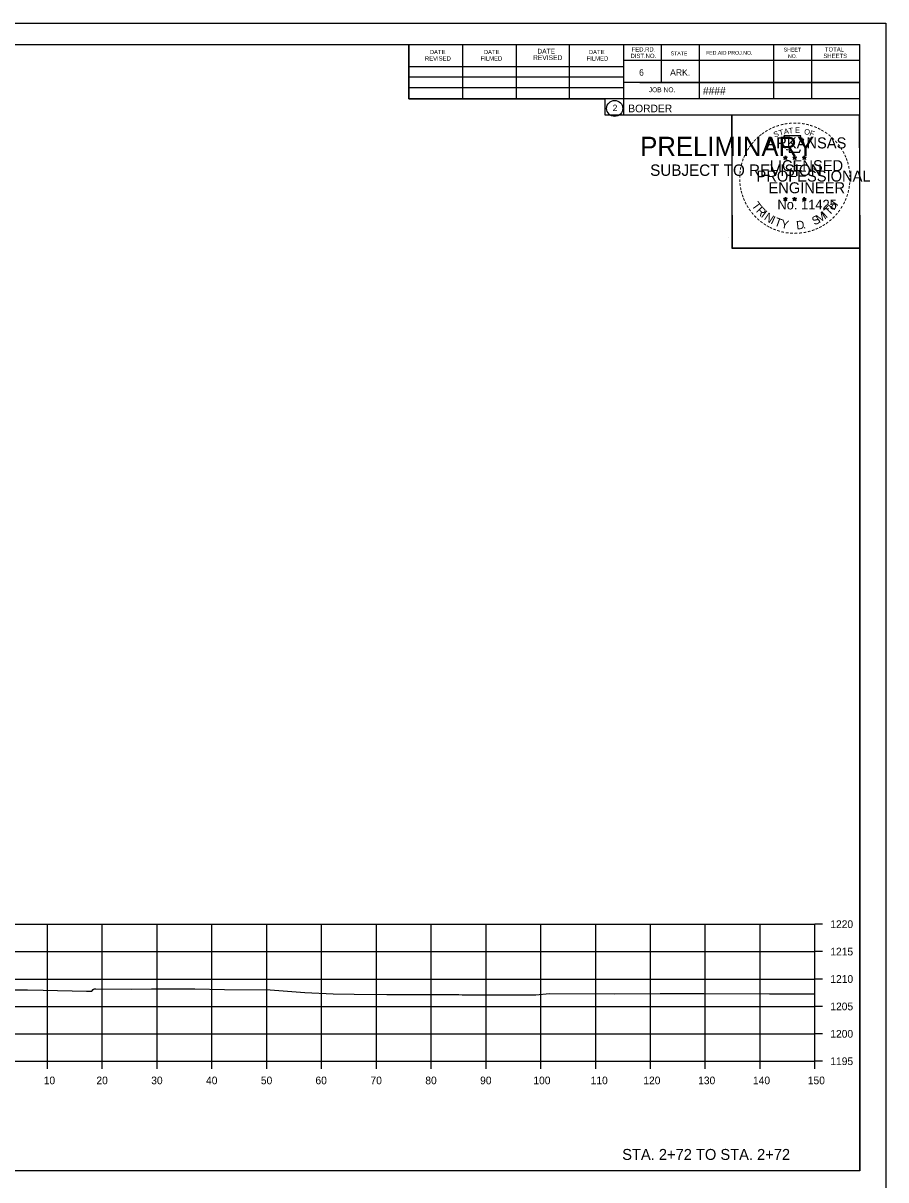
# Model space of a CAD drawing. Extents: x -70 to 701944, y -4 to 666871.
# Drawn here: x 667205.6 to 667363, y 653443.1 to 653654.1 of the extents above; entities that cross this region are included whole.
import ezdxf

# ---------------------------------------------------------------- set-up
doc = ezdxf.new("R2010")
doc.units = 0
for name, color, linetype in [('R_Axis', 7, 'Continuous'), ('R_Axis Annot', 7, 'Continuous'), ('R_Border', 7, 'Continuous'), ('R_Border PE', 7, 'Continuous'), ('R_Border Prem', 7, 'Continuous'), ('R_Draft', 7, 'Continuous'), ('R_Exist Surface', 7, 'Continuous'), ('R_Grid', 7, 'Continuous'), ('R_No Plot', 7, 'Continuous')]:
    doc.layers.add(name, color=color, linetype=linetype)

msp = doc.modelspace()

# ---------------------------------------------------------------- linework, layer by layer
at = {"layer": 'R_Axis'}
for p, q in [((667350.03, 653464.74), (667350.03, 653489.74)), ((667351.43, 653489.74), (667350.03, 653489.74)), ((667351.43, 653484.74), (667350.03, 653484.74)), ((667351.43, 653479.74), (667350.03, 653479.74)), ((667351.43, 653474.74), (667350.03, 653474.74)), ((667351.43, 653469.74), (667350.03, 653469.74)), ((667050.03, 653464.74), (667350.03, 653464.74)), ((667210.03, 653463.34), (667210.03, 653464.74)), ((667220.03, 653463.34), (667220.03, 653464.74)), ((667230.03, 653463.34), (667230.03, 653464.74)), ((667240.03, 653463.34), (667240.03, 653464.74)), ((667250.03, 653463.34), (667250.03, 653464.74)), ((667260.03, 653463.34), (667260.03, 653464.74)), ((667270.03, 653463.34), (667270.03, 653464.74)), ((667280.03, 653463.34), (667280.03, 653464.74)), ((667290.03, 653463.34), (667290.03, 653464.74)), ((667300.03, 653463.34), (667300.03, 653464.74)), ((667310.03, 653463.34), (667310.03, 653464.74)), ((667320.03, 653463.34), (667320.03, 653464.74)), ((667330.03, 653463.34), (667330.03, 653464.74)), ((667340.03, 653463.34), (667340.03, 653464.74)), ((667350.03, 653463.34), (667350.03, 653464.74)), ((667351.43, 653464.74), (667350.03, 653464.74))]:
    msp.add_line(p, q, dxfattribs=at)
at = {"layer": 'R_Border'}
for p, q in [((667042.03, 653650.2), (667358.21, 653650.2)), ((667275.95, 653640.32), (667275.95, 653650.2)), ((667285.81, 653640.32), (667285.81, 653650)), ((667295.57, 653640.32), (667295.57, 653650)), ((667305.25, 653640.32), (667305.25, 653650)), ((667315.11, 653650.2), (667315.11, 653637.4)), ((667321.95, 653650.2), (667321.95, 653643.26)), ((667328.89, 653650.2), (667328.89, 653640.32)), ((667342.47, 653650.2), (667342.47, 653640.32)), ((667349.41, 653650.2), (667349.41, 653640.32)), ((667358.21, 653444.74), (667358.21, 653650.2)), ((667358.21, 653647.26), (667315.11, 653647.26)), ((667358.21, 653647.28), (667358.21, 653647.28)), ((667275.95, 653646.18), (667315.11, 653646.18)), ((667275.95, 653644.32), (667315.11, 653644.32)), ((667358.21, 653643.26), (667315.11, 653643.26)), ((667318.07, 653643.26), (667358.21, 653643.26)), ((667275.95, 653640.32), (667275.95, 653642.38)), ((667275.95, 653642.38), (667315.11, 653642.38)), ((667358.21, 653640.32), (667275.95, 653640.32)), ((667315.11, 653637.4), (667358.21, 653637.4)), ((667358.21, 653444.74), (667042.03, 653444.74))]:
    msp.add_line(p, q, dxfattribs=at)
msp.add_circle((667313.5, 653638.54), 1.47, dxfattribs=at)
at = {"layer": 'R_Border PE'}
for p, q in [((667344.3, 653629.66), (667344.65, 653629.55)), ((667344.3, 653629.66), (667344.55, 653629.61)), ((667344.3, 653629.66), (667344.54, 653629.54)), ((667344.43, 653629.25), (667344.65, 653629.55)), ((667344.43, 653629.25), (667344.56, 653629.5)), ((667344.43, 653629.25), (667344.65, 653629.47)), ((667344.65, 653629.91), (667344.61, 653629.66)), ((667344.65, 653629.55), (667344.65, 653629.91)), ((667344.65, 653629.91), (667344.7, 653629.66)), ((667344.99, 653629.66), (667344.65, 653629.55)), ((667344.86, 653629.25), (667344.65, 653629.55)), ((667344.86, 653629.25), (667344.65, 653629.47)), ((667344.99, 653629.66), (667344.71, 653629.61)), ((667344.86, 653629.25), (667344.72, 653629.54)), ((667344.99, 653629.66), (667344.79, 653629.56)), ((667345.97, 653629.66), (667346.32, 653629.55)), ((667345.97, 653629.66), (667346.22, 653629.61)), ((667345.97, 653629.66), (667346.21, 653629.54)), ((667346.1, 653629.25), (667346.32, 653629.55)), ((667346.1, 653629.25), (667346.23, 653629.5)), ((667346.1, 653629.25), (667346.32, 653629.47)), ((667346.32, 653629.91), (667346.28, 653629.66)), ((667346.32, 653629.55), (667346.32, 653629.91)), ((667346.32, 653629.91), (667346.37, 653629.66)), ((667346.66, 653629.66), (667346.32, 653629.55)), ((667346.53, 653629.25), (667346.32, 653629.55)), ((667346.53, 653629.25), (667346.32, 653629.47)), ((667346.66, 653629.66), (667346.38, 653629.61)), ((667346.53, 653629.25), (667346.39, 653629.54)), ((667346.66, 653629.66), (667346.46, 653629.56)), ((667347.73, 653629.65), (667348.08, 653629.54)), ((667347.73, 653629.65), (667347.99, 653629.6)), ((667347.73, 653629.65), (667347.97, 653629.53)), ((667347.87, 653629.24), (667348.08, 653629.54)), ((667347.87, 653629.24), (667347.99, 653629.48)), ((667347.87, 653629.24), (667348.08, 653629.46)), ((667348.08, 653629.9), (667348.04, 653629.65)), ((667348.08, 653629.54), (667348.08, 653629.9)), ((667348.08, 653629.9), (667348.13, 653629.65)), ((667348.43, 653629.65), (667348.08, 653629.54)), ((667348.29, 653629.24), (667348.08, 653629.54)), ((667348.29, 653629.24), (667348.08, 653629.45)), ((667348.43, 653629.65), (667348.14, 653629.6)), ((667348.29, 653629.24), (667348.16, 653629.53)), ((667348.43, 653629.65), (667348.22, 653629.55)), ((667344.29, 653622.09), (667344.64, 653621.98)), ((667344.29, 653622.09), (667344.55, 653622.04)), ((667344.29, 653622.09), (667344.53, 653621.96)), ((667344.43, 653621.68), (667344.64, 653621.98)), ((667344.43, 653621.68), (667344.55, 653621.92)), ((667344.43, 653621.68), (667344.64, 653621.9)), ((667344.64, 653622.34), (667344.6, 653622.09)), ((667344.64, 653621.98), (667344.64, 653622.34)), ((667344.64, 653622.34), (667344.69, 653622.09)), ((667344.99, 653622.09), (667344.64, 653621.98)), ((667344.86, 653621.68), (667344.64, 653621.98)), ((667344.86, 653621.68), (667344.64, 653621.89)), ((667344.99, 653622.09), (667344.7, 653622.04)), ((667344.86, 653621.68), (667344.72, 653621.97)), ((667344.99, 653622.09), (667344.79, 653621.98)), ((667345.96, 653622.09), (667346.31, 653621.98)), ((667345.96, 653622.09), (667346.22, 653622.04)), ((667345.96, 653622.09), (667346.2, 653621.96)), ((667346.1, 653621.68), (667346.31, 653621.98)), ((667346.1, 653621.68), (667346.22, 653621.92)), ((667346.1, 653621.68), (667346.31, 653621.9)), ((667346.31, 653622.34), (667346.27, 653622.09)), ((667346.31, 653621.98), (667346.31, 653622.34)), ((667346.31, 653622.34), (667346.36, 653622.09)), ((667346.66, 653622.09), (667346.31, 653621.98)), ((667346.53, 653621.68), (667346.31, 653621.98)), ((667346.53, 653621.68), (667346.31, 653621.89)), ((667346.66, 653622.09), (667346.37, 653622.04)), ((667346.53, 653621.68), (667346.39, 653621.97)), ((667346.66, 653622.09), (667346.46, 653621.98)), ((667347.73, 653622.08), (667348.08, 653621.97)), ((667347.73, 653622.08), (667347.98, 653622.03)), ((667347.73, 653622.08), (667347.97, 653621.95)), ((667347.86, 653621.67), (667348.08, 653621.97)), ((667347.86, 653621.67), (667347.99, 653621.91)), ((667347.86, 653621.67), (667348.08, 653621.89)), ((667348.08, 653622.33), (667348.04, 653622.08)), ((667348.08, 653621.97), (667348.08, 653622.33)), ((667348.08, 653622.33), (667348.13, 653622.08)), ((667348.43, 653622.08), (667348.08, 653621.97)), ((667348.29, 653621.67), (667348.08, 653621.97)), ((667348.29, 653621.67), (667348.08, 653621.88)), ((667348.43, 653622.08), (667348.14, 653622.03)), ((667348.29, 653621.67), (667348.16, 653621.96)), ((667348.43, 653622.08), (667348.22, 653621.97))]:
    msp.add_line(p, q, dxfattribs=at)
for points in [[(667344.34, 653633.54), (667344.61, 653632.71)], [(667347.85, 653632.62), (667347.99, 653632.9), (667347.31, 653632.88), (667347.46, 653633.54), (667344.34, 653633.54)], [(667344.83, 653631.11), (667344.83, 653631.03), (667345.39, 653631.01), (667345.34, 653630.54), (667347.21, 653630.54), (667347.41, 653631.07)], [(667344.65, 653629.91), (667344.86, 653629.25), (667344.3, 653629.66), (667344.99, 653629.66), (667344.43, 653629.25), (667344.65, 653629.91)], [(667346.32, 653629.91), (667346.53, 653629.25), (667345.97, 653629.66), (667346.66, 653629.66), (667346.1, 653629.25), (667346.32, 653629.91)], [(667348.08, 653629.9), (667348.29, 653629.24), (667347.73, 653629.65), (667348.43, 653629.65), (667347.87, 653629.24), (667348.08, 653629.9)], [(667344.64, 653622.34), (667344.86, 653621.68), (667344.29, 653622.09), (667344.99, 653622.09), (667344.43, 653621.68), (667344.64, 653622.34)], [(667346.31, 653622.34), (667346.53, 653621.68), (667345.96, 653622.09), (667346.66, 653622.09), (667346.1, 653621.68), (667346.31, 653622.34)], [(667348.08, 653622.33), (667348.29, 653621.67), (667347.73, 653622.08), (667348.43, 653622.08), (667347.86, 653621.67), (667348.08, 653622.33)]]:
    msp.add_lwpolyline(points, dxfattribs=at)
for centre, radius in [((667344.65, 653629.55), 0.172), ((667344.65, 653629.55), 0.145), ((667344.65, 653629.55), 0.116), ((667344.65, 653629.55), 0.0991), ((667344.65, 653629.55), 0.0747), ((667344.65, 653629.55), 0.0495), ((667344.65, 653629.55), 0.0296), ((667346.32, 653629.55), 0.172), ((667346.32, 653629.55), 0.145), ((667346.32, 653629.55), 0.116), ((667346.32, 653629.55), 0.0991), ((667346.32, 653629.55), 0.0747), ((667346.32, 653629.55), 0.0495), ((667346.32, 653629.55), 0.0296), ((667348.08, 653629.54), 0.172), ((667348.08, 653629.54), 0.145), ((667348.08, 653629.54), 0.116), ((667348.08, 653629.54), 0.0991), ((667348.08, 653629.54), 0.0747), ((667348.08, 653629.54), 0.0495), ((667348.08, 653629.54), 0.0296), ((667344.64, 653621.97), 0.172), ((667344.64, 653621.97), 0.145), ((667344.64, 653621.97), 0.116), ((667344.64, 653621.97), 0.0991), ((667344.64, 653621.97), 0.0747), ((667344.64, 653621.97), 0.0495), ((667344.64, 653621.97), 0.0296), ((667346.31, 653621.97), 0.172), ((667346.31, 653621.97), 0.145), ((667346.31, 653621.97), 0.116), ((667346.31, 653621.97), 0.0991), ((667346.31, 653621.97), 0.0747), ((667346.31, 653621.97), 0.0495), ((667346.31, 653621.97), 0.0296), ((667348.08, 653621.96), 0.172), ((667348.08, 653621.96), 0.145), ((667348.08, 653621.96), 0.116), ((667348.08, 653621.96), 0.0991), ((667348.08, 653621.96), 0.0747), ((667348.08, 653621.96), 0.0495), ((667348.08, 653621.96), 0.0296)]:
    msp.add_circle(centre, radius, dxfattribs=at)
at = {"layer": 'R_Exist Surface'}
msp.add_lwpolyline([(667200.89, 653477.78), (667205.63, 653477.77), (667206.38, 653477.77), (667209.25, 653477.69), (667217.16, 653477.53), (667217.42, 653477.54), (667218.1, 653477.51), (667218.38, 653477.83), (667218.52, 653477.97), (667218.72, 653477.96), (667218.82, 653477.96), (667225.3, 653477.91), (667228.98, 653477.95), (667229.18, 653477.95), (667229.2, 653477.95), (667234.9, 653477.97), (667236.9, 653477.92), (667242.31, 653477.84), (667250.65, 653477.76), (667256.99, 653477.26), (667262.17, 653477.06), (667265.95, 653477), (667271.96, 653476.91), (667285.08, 653476.89), (667285.7, 653476.88), (667299.02, 653476.86), (667299.1, 653476.88), (667301.63, 653477.12), (667313.51, 653477.06), (667321.78, 653477.08), (667329.76, 653477.11), (667341.72, 653477.06), (667350.03, 653477.01)], dxfattribs=at)
at = {"layer": 'R_Grid'}
for p, q in [((667050.03, 653489.74), (667350.03, 653489.74)), ((667210.03, 653464.74), (667210.03, 653489.74)), ((667220.03, 653464.74), (667220.03, 653489.74)), ((667230.03, 653464.74), (667230.03, 653489.74)), ((667240.03, 653464.74), (667240.03, 653489.74)), ((667250.03, 653464.74), (667250.03, 653489.74)), ((667260.03, 653464.74), (667260.03, 653489.74)), ((667270.03, 653464.74), (667270.03, 653489.74)), ((667280.03, 653464.74), (667280.03, 653489.74)), ((667290.03, 653464.74), (667290.03, 653489.74)), ((667300.03, 653464.74), (667300.03, 653489.74)), ((667310.03, 653464.74), (667310.03, 653489.74)), ((667320.03, 653464.74), (667320.03, 653489.74)), ((667330.03, 653464.74), (667330.03, 653489.74)), ((667340.03, 653464.74), (667340.03, 653489.74)), ((667350.03, 653464.74), (667350.03, 653489.74)), ((667050.03, 653484.74), (667350.03, 653484.74)), ((667050.03, 653479.74), (667350.03, 653479.74)), ((667050.03, 653474.74), (667350.03, 653474.74)), ((667050.03, 653469.74), (667350.03, 653469.74)), ((667050.03, 653464.74), (667350.03, 653464.74))]:
    msp.add_line(p, q, dxfattribs=at)
at = {"layer": 'R_No Plot'}
for p, q in [((667029.63, 653654.1), (667362.97, 653654.1)), ((667334.25, 653614.95), (667334.25, 653614.95))]:
    msp.add_line(p, q, dxfattribs=at)
for points in [[(667029.63, 653654.1), (667362.97, 653654.1), (667362.97, 653440.76), (667029.63, 653440.76)], [(667275.95, 653650.2), (667275.95, 653640.32), (667311.69, 653640.32), (667311.69, 653637.4), (667334.88, 653637.4), (667334.88, 653613.07), (667358.21, 653613.07), (667358.21, 653444.74), (667042.03, 653444.74), (667042.03, 653650.2)], [(667334.88, 653637.4), (667358.09, 653637.4), (667358.21, 653613.07), (667335.01, 653613.07)]]:
    msp.add_lwpolyline(points, close=True, dxfattribs=at)

# ---------------------------------------------------------------- texts
at = {"layer": 'R_Axis Annot'}
for s, p in [('1220', (667352.83, 653489.04)), ('1215', (667352.83, 653484.04)), ('1210', (667352.83, 653479.04)), ('1205', (667352.83, 653474.04)), ('1200', (667352.83, 653469.04)), ('1195', (667352.83, 653464.04)), ('10', (667209.34, 653460.54)), ('20', (667218.95, 653460.54)), ('30', (667228.95, 653460.54)), ('40', (667238.95, 653460.54)), ('50', (667248.95, 653460.54)), ('60', (667258.91, 653460.54)), ('70', (667268.95, 653460.54)), ('80', (667278.95, 653460.54)), ('90', (667288.95, 653460.54)), ('100', (667298.66, 653460.54)), ('110', (667309.11, 653460.54)), ('120', (667318.72, 653460.54)), ('130', (667328.72, 653460.54)), ('140', (667338.72, 653460.54)), ('150', (667348.72, 653460.54))]:
    msp.add_text(s, height=1.4, dxfattribs=at).set_placement(p)
at = {"layer": 'R_Border'}
for s, height, p in [('DATE', 0.782, (667279.75, 653648.44)), ('DATE', 0.782, (667289.61, 653648.44)), ('DATE', 0.879, (667299.39, 653648.54)), ('DATE', 0.782, (667308.77, 653648.44)), ('FED.RD.', 0.782, (667316.59, 653648.92)), ('SHEET', 0.684, (667344.33, 653648.92)), ('TOTAL', 0.782, (667351.85, 653648.92)), ('REVISED', 0.782, (667278.87, 653647.26)), ('FILMED', 0.782, (667289.03, 653647.26)), ('REVISED', 0.879, (667298.61, 653647.36)), ('FILMED', 0.782, (667308.37, 653647.26)), ('DIST.NO.', 0.782, (667316.39, 653647.74)), ('STATE', 0.684, (667323.71, 653648.24)), ('FED.AID PROJ.NO.', 0.684, (667330.17, 653648.34)), ('NO.', 0.684, (667345.11, 653647.74)), ('SHEETS', 0.782, (667351.57, 653647.74)), ('6', 1.17, (667317.95, 653644.52)), ('ARK.', 1.172, (667323.61, 653644.52)), ('JOB NO.', 0.879, (667319.71, 653641.5)), ('####', 1.4, (667329.59, 653641.06)), ('2', 1.17, (667313.12, 653638.05)), ('BORDER', 1.4, (667315.98, 653637.83))]:
    msp.add_text(s, height=height, rotation=360, dxfattribs=at).set_placement(p)
at = {"layer": 'R_Border PE'}
for s, height, rotation, p in [('-', 1.6, 34.0636, (667341.22, 653633.71)), ('-', 1.6, 28.7918, (667341.82, 653634.08)), ('-', 1.6, 24.3072, (667342.45, 653634.4)), ('-', 1.6, 19.1761, (667343.09, 653634.66)), ('T', 1, 16.4036, (667343.61, 653633.55)), ('-', 1.6, 13.6301, (667343.84, 653634.91)), ('A', 1, 11.2132, (667344.43, 653633.8)), ('-', 1.6, 10.2193, (667344.52, 653635.07)), ('T', 1, 6.0228, (667345.28, 653633.96)), ('-', 1.6, 5.8968, (667345.24, 653635.18)), ('-', 1.6, 0.1862, (667346.02, 653635.25)), ('E', 1, 0.8323, (667346.39, 653634.07)), ('-', 1.6, 357.743, (667346.74, 653635.24)), ('-', 1.6, 352.1617, (667347.48, 653635.18)), ('O', 1, 350.4515, (667347.99, 653633.86)), ('-', 1.6, 347.2049, (667348.2, 653635.07)), ('F', 1, 340.0707, (667348.95, 653633.64)), ('-', 1.6, 342.3362, (667348.84, 653634.91)), ('-', 1.6, 337.8551, (667349.57, 653634.69)), ('-', 1.6, 334.1211, (667350.2, 653634.42)), ('-', 1.6, 329.6409, (667350.78, 653634.13)), ('-', 1.6, 50.6142, (667338.89, 653631.55)), ('-', 1.6, 48.423, (667339.29, 653632.04)), ('-', 1.6, 42.9622, (667339.74, 653632.52)), ('-', 1.6, 38.9507, (667340.17, 653632.94)), ('-', 1.6, 36.2317, (667340.65, 653633.31)), ('ARKANSAS', 2, 360, (667341.19, 653631.25)), ('S', 1, 21.594, (667342.69, 653633.22)), ('-', 1.6, 325.8627, (667351.43, 653633.77)), ('-', 1.6, 320.5297, (667352.04, 653633.35)), ('-', 1.6, 315.5786, (667352.63, 653632.86)), ('-', 1.6, 309.8797, (667353.2, 653632.31)), ('-', 1.6, 62.8713, (667337.83, 653629.85)), ('-', 1.6, 58.0706, (667338.15, 653630.46)), ('-', 1.6, 54.2325, (667338.47, 653630.99)), ('-', 1.6, 306.6522, (667353.73, 653631.71)), ('-', 1.4, 303.6753, (667354.21, 653631.14)), ('-', 1.6, 299.6684, (667354.53, 653630.53)), ('-', 1.6, 75.461, (667337.16, 653627.89)), ('-', 1.6, 72.3945, (667337.36, 653628.61)), ('-', 1.6, 67.7743, (667337.58, 653629.24)), ('LICENSED', 2, 360, (667341.79, 653627.1)), ('DWB', 0.01, 360, (667344.63, 653629.54)), ('DWB', 0.01, 360, (667346.3, 653629.54)), ('DWB', 0.01, 360, (667348.07, 653629.53)), ('-', 1.6, 294.6628, (667354.86, 653629.92)), ('-', 1.6, 290.5728, (667355.11, 653629.34)), ('-', 1.6, 285.1233, (667355.35, 653628.76)), ('-', 1.6, 89.0622, (667336.93, 653625.79)), ('-', 1.6, 85.1863, (667336.95, 653626.49)), ('-', 1.6, 81.2013, (667337.03, 653627.18)), ('PROFESSIONAL', 2, 360, (667339.37, 653625.2)), ('-', 1.6, 280.5493, (667355.55, 653628.02)), ('-', 1.6, 276.5962, (667355.71, 653627.25)), ('-', 1.6, 274.3301, (667355.77, 653626.53)), ('-', 1.6, 94.1959, (667336.96, 653625.06)), ('-', 1.6, 98.9479, (667337.03, 653624.39)), ('-', 1.6, 101.7149, (667337.17, 653623.66)), ('ENGINEER', 2, 360, (667341.55, 653623.07)), ('-', 1.6, 260.9953, (667355.71, 653624.58)), ('-', 1.6, 263.5172, (667355.79, 653625.23)), ('-', 1.6, 269.9407, (667355.8, 653625.9)), ('-', 1.6, 105.4578, (667337.33, 653623.07)), ('-', 1.6, 109.0874, (667337.55, 653622.44)), ('-', 1.6, 114.0643, (667337.8, 653621.84)), ('No. 11425', 1.757, 360, (667343.18, 653620.12)), ('DWB', 0.01, 360, (667344.63, 653621.97)), ('DWB', 0.01, 360, (667346.3, 653621.97)), ('DWB', 0.01, 360, (667348.07, 653621.96)), ('H', 1.54, 54.6088, (667353.52, 653619.85)), ('-', 1.6, 247.8887, (667355.2, 653622.51)), ('-', 1.6, 252.8681, (667355.42, 653623.18)), ('-', 1.6, 255.7626, (667355.6, 653623.9)), ('-', 1.6, 115.7289, (667338.1, 653621.22)), ('-', 1.6, 120.4471, (667338.46, 653620.64)), ('-', 1.6, 125.8934, (667338.86, 653620.07)), ('-', 1.6, 130.7181, (667339.33, 653619.52)), ('T', 1.54, 306.0406, (667338.4, 653620.81)), ('R', 1.54, 314.005, (667339.17, 653619.77)), ('I', 1.54, 321.9694, (667340.07, 653618.83)), ('M', 1.54, 32.6563, (667350.79, 653617.58)), ('I', 1.54, 42.1136, (667352.07, 653618.43)), ('T', 1.54, 46.6444, (667352.63, 653618.91)), ('-', 1.6, 233.8452, (667354.14, 653620.47)), ('-', 1.6, 239.0712, (667354.54, 653621.13)), ('-', 1.6, 244.6197, (667354.94, 653621.88)), ('-', 1.6, 134.2238, (667339.84, 653618.98)), ('-', 1.6, 138.9338, (667340.37, 653618.51)), ('-', 1.6, 144.6463, (667340.92, 653618.11)), ('-', 1.6, 148.0898, (667341.49, 653617.74)), ('N', 1.54, 326.5002, (667340.63, 653618.36)), ('I', 1.54, 335.3603, (667341.84, 653617.58)), ('T', 1.54, 339.8912, (667342.5, 653617.25)), ('Y', 1.54, 347.8556, (667343.72, 653616.8)), ('D', 1.54, 6.3969, (667346.7, 653616.44)), ('S', 1.54, 26.9312, (667349.95, 653617.18)), ('-', 1.6, 215.7363, (667352.16, 653618.36)), ('-', 1.6, 221.0851, (667352.71, 653618.84)), ('-', 1.6, 225.7653, (667353.23, 653619.34)), ('-', 1.6, 231.2538, (667353.71, 653619.91)), ('-', 1.6, 151.5704, (667342.06, 653617.41)), ('-', 1.6, 154.6002, (667342.59, 653617.16)), ('-', 1.6, 158.5612, (667343.21, 653616.91)), ('-', 1.6, 162.7983, (667343.9, 653616.7)), ('-', 1.6, 167.5555, (667344.61, 653616.53)), ('-', 1.6, 173.1155, (667345.38, 653616.42)), ('-', 1.6, 176.5183, (667346.13, 653616.37)), ('-', 1.6, 181.5918, (667346.88, 653616.39)), ('-', 1.6, 185.8167, (667347.69, 653616.47)), ('-', 1.6, 191.2858, (667348.42, 653616.6)), ('.', 1.54, 13.7642, (667347.9, 653616.57)), ('-', 1.6, 195.4743, (667349.15, 653616.8)), ('-', 1.6, 200.7184, (667349.83, 653617.04)), ('-', 1.6, 204.2516, (667350.45, 653617.31)), ('-', 1.6, 207.3568, (667351.07, 653617.63)), ('-', 1.6, 212.2491, (667351.63, 653617.98))]:
    msp.add_text(s, height=height, rotation=rotation, dxfattribs=at).set_placement(p)
at = {"layer": 'R_Border Prem'}
for s, height, p in [('PRELIMINARY', 3.5, (667318.16, 653629.87)), ('DWB', 0.01, (667318.91, 653631.72)), ('SUBJECT TO REVISION', 2.0751, (667319.97, 653626.24))]:
    msp.add_text(s, height=height, rotation=360, dxfattribs=at).set_placement(p)
at = {"layer": 'R_Draft'}
msp.add_text('STA. 2+72 TO STA. 2+72', height=2, dxfattribs=at).set_placement((667314.87, 653446.74))

doc.saveas('drawing.dxf')
